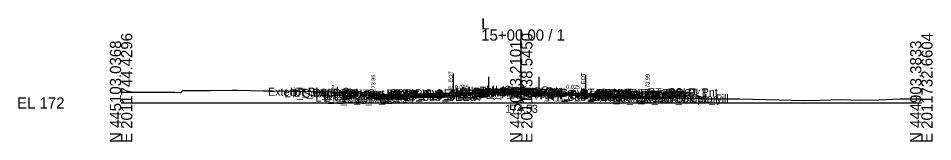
# Model space of a CAD drawing. Extents: x -26 to 4203, y -10 to 9526.
# Drawn here: x -25.7 to 202.8, y 4990.3 to 5021.2 of the extents above; entities that cross this region are included whole.
import ezdxf

# ---------------------------------------------------------------- set-up
doc = ezdxf.new("R2010")
doc.units = 0
for name, color, linetype in [('Default', 7, 'Continuous'), ('Exist CMT Pavement', 7, 'Continuous'), ('Exist Cross Section Cell', 7, 'Continuous'), ('Exist XS Center Line Elevation Label', 7, 'Continuous'), ('Exist XS Ground Line', 7, 'Continuous'), ('Prop CMT Conc Surface', 7, 'Continuous'), ('Prop CMT Concrete Structures', 7, 'Continuous'), ('Prop CMT Pvmt Course 1', 7, 'Continuous'), ('Prop CMT Pvmt Course 1 CG', 7, 'Continuous'), ('Prop CMT Pvmt Course 1 Wedge', 7, 'Continuous'), ('Prop CMT Pvmt Course 2', 7, 'Continuous'), ('Prop CMT Pvmt Course 2 Wedge', 7, 'Continuous'), ('Prop CMT Pvmt Course 3', 7, 'Continuous'), ('Prop CMT Pvmt Surface', 7, 'Continuous'), ('Prop CMT Pvmt Wedge Surface 1', 7, 'Continuous'), ('Prop CMT Pvmt Wedge Surface 2', 7, 'Continuous'), ('Prop CMT Pvmt Wedge Surface 3', 7, 'Continuous'), ('Prop CMT Slope Grass', 7, 'Continuous'), ('Prop CMT Subgrade Earthwork', 7, 'Continuous'), ('Prop XS Hydro Elevations', 7, 'Continuous'), ('Prop XS Label Text', 7, 'Continuous'), ('Prop XS SE Text', 7, 'Continuous'), ('Prop XS Side Slope Text', 7, 'Continuous'), ('Scratch_Level_0', 7, 'Continuous'), ('Scratch_Level_3', 7, 'Continuous')]:
    doc.layers.add(name, color=color, linetype=linetype)

msp = doc.modelspace()

# ---------------------------------------------------------------- linework, layer by layer
at = {"layer": 'Exist CMT Pavement'}
for points in [[(100, 5002.53), (99.08, 5002.54), (98.16, 5002.55), (97.34, 5002.55), (95.64, 5002.54), (94.98, 5002.54), (94.18, 5002.54), (93.53, 5002.54), (93.15, 5002.53), (91.11, 5002.52), (90.67, 5002.51), (90.28, 5002.51), (88.12, 5002.47), (85.72, 5002.44), (85.61, 5002.44), (85.26, 5002.43), (83.89, 5002.41), (83.13, 5002.4), (83, 5002.4), (81.97, 5002.39), (81.35, 5002.38), (81.35, 5002.38)], [(100, 5002.53), (100.66, 5002.53), (102.05, 5002.5), (103.13, 5002.48), (104.11, 5002.47), (104.98, 5002.47), (105.23, 5002.46), (105.64, 5002.45), (106.79, 5002.4), (108.16, 5002.35), (109.72, 5002.29), (110.69, 5002.26), (111.54, 5002.22), (113.18, 5002.14), (115.03, 5002.06), (115.68, 5002.04), (115.83, 5002.03), (116.08, 5002.02), (116.46, 5001.99), (117.25, 5001.94)]]:
    msp.add_lwpolyline(points, dxfattribs=at)
at = {"layer": 'Exist Cross Section Cell'}
for p, q in [((100, 5000), (100, 5018.37)), ((0, 5000), (100, 5000)), ((100, 5000), (200, 5000))]:
    msp.add_line(p, q, dxfattribs=at)
at = {"layer": 'Exist XS Ground Line'}
msp.add_lwpolyline([(0, 5002.68), (13.44, 5002.7), (15.02, 5002.59), (15.44, 5003.09), (22.37, 5003.11), (27.73, 5003.23), (29.13, 5003.23), (35.62, 5003.06), (37.77, 5003.03), (42.17, 5002.94), (44.79, 5002.98), (49.29, 5002.88), (51.69, 5002.82), (62.74, 5002.38), (66.97, 5002.11), (77.65, 5002.31), (81.35, 5002.38), (81.97, 5002.39), (83, 5002.4), (83.89, 5002.41), (85.26, 5002.43), (85.72, 5002.44), (88.12, 5002.47), (90.28, 5002.51), (90.67, 5002.51), (91.11, 5002.52), (93.15, 5002.53), (93.53, 5002.54), (94.18, 5002.54), (94.98, 5002.54), (95.64, 5002.54), (97.34, 5002.55), (98.16, 5002.55), (99.08, 5002.54), (100, 5002.53), (100.66, 5002.53), (102.05, 5002.5), (103.13, 5002.48), (104.11, 5002.47), (104.98, 5002.47), (105.64, 5002.45), (106.79, 5002.4), (108.16, 5002.35), (109.72, 5002.29), (110.69, 5002.26), (111.54, 5002.22), (113.18, 5002.14), (115.03, 5002.06), (116.08, 5002.02), (116.46, 5001.99), (117.25, 5001.94), (127.23, 5001.69), (134.52, 5001.49), (142.12, 5001.18), (144.54, 5001.12), (147.26, 5001.04), (154.56, 5001.01), (161.05, 5000.88), (164.58, 5000.8), (170.51, 5000.64), (174.6, 5000.72), (179.97, 5000.82), (184.61, 5000.72), (189.43, 5000.77), (194.63, 5000.99), (198.89, 5001.02), (200, 5001.01)], dxfattribs=at)
at = {"layer": 'Prop CMT Conc Surface'}
for points in [[(136.07, 5002.58), (141.07, 5002.68)], [(63.05, 5001.86), (63.05, 5002.36), (62.55, 5002.36)], [(65.05, 5001.99), (63.05, 5001.86)], [(129.57, 5002.12), (131.57, 5001.99)], [(131.57, 5001.99), (131.57, 5002.49), (132.07, 5002.49)]]:
    msp.add_lwpolyline(points, dxfattribs=at)
at = {"layer": 'Prop CMT Concrete Structures'}
for points in [[(98.45, 5003.29), (92.66, 5003.08), (91.91, 5002.83), (91.9, 5002.66)], [(91.9, 5002.66), (100, 5002.86), (104.49, 5002.75)], [(104.49, 5002.75), (104.48, 5002.92), (103.73, 5003.17), (98.45, 5003.29)], [(141.07, 5002.68), (136.07, 5002.58)], [(136.07, 5002.58), (136.07, 5002.25)], [(141.07, 5002.35), (141.07, 5002.68)], [(65.05, 5001.99), (63.05, 5001.86), (63.05, 5002.36), (62.55, 5002.36)], [(62.55, 5002.36), (62.55, 5001.34), (65.05, 5001.41)], [(65.05, 5001.41), (65.05, 5001.99)], [(129.57, 5002.12), (131.57, 5001.99), (131.57, 5002.49), (132.07, 5002.49)], [(132.07, 5002.49), (132.07, 5001.48), (129.57, 5001.54)], [(129.57, 5001.54), (129.57, 5002.12)], [(136.07, 5002.25), (141.07, 5002.35)]]:
    msp.add_lwpolyline(points, dxfattribs=at)
at = {"layer": 'Prop CMT Pvmt Course 1'}
for points in [[(100, 5002.86), (65.05, 5001.99)], [(83, 5002.31), (100, 5002.74)], [(100, 5002.61), (100, 5002.86)], [(100, 5002.86), (129.57, 5002.12)], [(100, 5002.61), (100, 5002.86)], [(100, 5002.74), (100, 5002.61), (100, 5002.61)], [(116.08, 5002.34), (100, 5002.74)], [(100, 5002.74), (100, 5002.61), (100, 5002.61)], [(65.05, 5001.74), (81.35, 5002.15)], [(65.05, 5001.99), (65.05, 5001.74)], [(83, 5002.19), (83, 5002.31)], [(116.08, 5002.21), (116.08, 5002.34)], [(129.57, 5001.87), (117.25, 5002.18)], [(129.57, 5002.12), (129.57, 5001.87)]]:
    msp.add_lwpolyline(points, dxfattribs=at)
at = {"layer": 'Prop CMT Pvmt Course 1 CG'}
for points in [[(65.05, 5001.41), (62.05, 5001.33), (61.7, 5000.99)], [(61.7, 5000.99), (65.05, 5001.07)], [(65.05, 5001.07), (65.05, 5001.41)], [(129.57, 5001.54), (132.57, 5001.47), (132.91, 5001.12)], [(129.57, 5001.21), (129.57, 5001.54)], [(132.91, 5001.12), (129.57, 5001.21)]]:
    msp.add_lwpolyline(points, dxfattribs=at)
at = {"layer": 'Prop CMT Pvmt Course 1 Wedge'}
for points in [[(100, 5002.61), (99.08, 5002.59), (98.16, 5002.57), (97.35, 5002.55), (97.34, 5002.55), (95.64, 5002.54), (94.98, 5002.54), (94.18, 5002.54), (93.53, 5002.54), (93.15, 5002.53), (91.11, 5002.52), (91.08, 5002.52)], [(91.11, 5002.52), (93.15, 5002.57), (93.53, 5002.58), (94.18, 5002.59), (94.98, 5002.61), (95.64, 5002.63), (97.34, 5002.67), (98.16, 5002.69), (99.08, 5002.71), (100, 5002.74)], [(100, 5002.61), (100, 5002.74)], [(100, 5002.74), (100, 5002.61)], [(116.08, 5002.21), (115.83, 5002.22), (115.68, 5002.22), (115.03, 5002.24), (113.18, 5002.28), (111.54, 5002.32), (110.69, 5002.35), (109.72, 5002.37), (108.16, 5002.41), (106.79, 5002.44), (105.64, 5002.47), (105.23, 5002.48), (104.98, 5002.49), (104.11, 5002.51), (103.13, 5002.53), (102.05, 5002.56), (100.66, 5002.6), (100, 5002.61)], [(91.08, 5002.52), (91.11, 5002.52)], [(116.08, 5002.34), (116.08, 5002.21)]]:
    msp.add_lwpolyline(points, dxfattribs=at)
at = {"layer": 'Prop CMT Pvmt Course 2'}
for points in [[(83, 5002.19), (65.05, 5001.74)], [(65.05, 5001.41), (81.35, 5001.81)], [(65.05, 5001.74), (65.05, 5001.41)], [(83, 5001.85), (83, 5002.19)], [(116.08, 5001.88), (116.08, 5002.21)], [(116.08, 5002.21), (129.57, 5001.87)], [(129.57, 5001.54), (117.25, 5001.85)], [(129.57, 5001.87), (129.57, 5001.54)]]:
    msp.add_lwpolyline(points, dxfattribs=at)
at = {"layer": 'Prop CMT Pvmt Course 2 Wedge'}
for points in [[(98.16, 5002.57), (99.08, 5002.59), (100, 5002.61)], [(100, 5002.53), (100, 5002.61)], [(100, 5002.61), (100, 5002.53)], [(100, 5002.61), (100.66, 5002.6), (102.05, 5002.56), (103.13, 5002.53), (104.11, 5002.51), (104.98, 5002.49), (105.23, 5002.48), (105.64, 5002.47), (106.79, 5002.44), (108.16, 5002.41), (109.72, 5002.37), (110.69, 5002.35), (111.54, 5002.32), (113.18, 5002.28), (115.03, 5002.24), (115.68, 5002.22), (115.83, 5002.22), (116.08, 5002.21)], [(97.35, 5002.55), (98.16, 5002.57)], [(100, 5002.53), (99.08, 5002.54), (98.16, 5002.55), (97.35, 5002.55)], [(117.25, 5001.94), (116.46, 5001.99), (116.08, 5002.02), (115.83, 5002.03), (115.68, 5002.04), (115.03, 5002.06), (113.18, 5002.14), (111.54, 5002.22), (110.69, 5002.26), (109.72, 5002.29), (108.16, 5002.35), (106.79, 5002.4), (105.64, 5002.45), (105.23, 5002.46), (104.98, 5002.47), (104.11, 5002.47), (103.13, 5002.48), (102.05, 5002.5), (100.66, 5002.53), (100, 5002.53)], [(116.08, 5002.21), (116.08, 5001.97)]]:
    msp.add_lwpolyline(points, dxfattribs=at)
at = {"layer": 'Prop CMT Pvmt Course 3'}
for points in [[(83, 5001.85), (65.05, 5001.41)], [(65.05, 5001.07), (83, 5001.52)], [(65.05, 5001.41), (65.05, 5001.07)], [(83, 5001.52), (83, 5001.85)], [(116.08, 5001.88), (129.57, 5001.54)], [(116.08, 5001.54), (116.08, 5001.88)], [(129.57, 5001.21), (116.08, 5001.54)], [(129.57, 5001.54), (129.57, 5001.21)]]:
    msp.add_lwpolyline(points, dxfattribs=at)
at = {"layer": 'Prop CMT Pvmt Surface'}
for points in [[(100, 5002.86), (65.05, 5001.99)], [(100, 5002.86), (129.57, 5002.12)]]:
    msp.add_lwpolyline(points, dxfattribs=at)
at = {"layer": 'Prop CMT Pvmt Wedge Surface 1'}
for points in [[(100, 5002.74), (83, 5002.31)], [(100, 5002.74), (116.08, 5002.34)], [(81.35, 5002.15), (65.05, 5001.74)], [(65.05, 5001.74), (65.05, 5001.99)], [(83, 5002.31), (83, 5002.19)], [(116.08, 5002.34), (116.08, 5002.21)], [(117.25, 5002.18), (129.57, 5001.87)], [(129.57, 5001.87), (129.57, 5002.12)]]:
    msp.add_lwpolyline(points, dxfattribs=at)
at = {"layer": 'Prop CMT Pvmt Wedge Surface 2'}
for points in [[(100, 5002.61), (83, 5002.19)], [(100, 5002.61), (116.08, 5002.21)], [(65.05, 5001.74), (65.05, 5001.99)], [(129.57, 5001.87), (129.57, 5002.12)]]:
    msp.add_lwpolyline(points, dxfattribs=at)
at = {"layer": 'Prop CMT Pvmt Wedge Surface 3'}
for points in [[(65.05, 5001.41), (65.05, 5001.99)], [(100, 5002.28), (83, 5001.85)], [(100, 5002.28), (116.08, 5001.88)], [(129.57, 5001.54), (129.57, 5002.12)]]:
    msp.add_lwpolyline(points, dxfattribs=at)
at = {"layer": 'Prop CMT Slope Grass'}
for p, q in [((52.32, 5002.79), (53.05, 5002.55)), ((141.57, 5002.68), (146.43, 5001.06))]:
    msp.add_line(p, q, dxfattribs=at)
for points in [[(132.07, 5002.49), (141.57, 5002.68)], [(62.55, 5002.36), (53.05, 5002.55)]]:
    msp.add_lwpolyline(points, dxfattribs=at)
at = {"layer": 'Prop CMT Subgrade Earthwork'}
for points in [[(65.05, 5001.07), (61.7, 5000.99), (60.29, 5002.4)], [(83, 5001.52), (65.05, 5001.07)], [(83, 5001.52), (83, 5002.4)], [(116.08, 5001.54), (116.08, 5002.02)], [(116.08, 5001.54), (129.57, 5001.21)], [(129.57, 5001.21), (132.91, 5001.12), (134.33, 5002.54)]]:
    msp.add_lwpolyline(points, dxfattribs=at)
at = {"layer": 'Prop XS Label Text'}
for p, q in [((83, 5007.4), (83, 5002.4)), ((116.08, 5007.02), (116.08, 5002.02))]:
    msp.add_line(p, q, dxfattribs=at)
at = {"layer": 'Scratch_Level_3'}
for p, q in [((91.9, 5002.66), (91.9, 5006.5)), ((104.49, 5002.75), (104.49, 5006.5))]:
    msp.add_line(p, q, dxfattribs=at)
msp.add_lwpolyline([(100, 5002.74), (100.66, 5002.72), (102.05, 5002.69), (103.13, 5002.66), (104.11, 5002.64), (104.98, 5002.61), (105.23, 5002.61), (105.64, 5002.6), (106.79, 5002.57), (108.16, 5002.53), (109.72, 5002.5), (110.69, 5002.47), (111.54, 5002.45), (113.18, 5002.41), (115.03, 5002.36), (115.68, 5002.35), (115.83, 5002.34), (116.08, 5002.34)], dxfattribs=at)

# ---------------------------------------------------------------- texts
at = {"layer": 'Default'}
msp.add_text('-', height=0.0001, dxfattribs=at).set_placement((0, 5000))
at = {"layer": 'Exist Cross Section Cell'}
for s, p in [('L', (90, 5018.37)), ('15+00.00 / 1', (90, 5015.57)), ('EL 172', (-26, 4998.6))]:
    msp.add_text(s, height=2.8, dxfattribs=at).set_placement(p)
for s, p in [('E 2011744.4296', (2.8, 4990)), ('E 2011738.5450', (102.8, 4990)), ('E 2011732.6604', (202.8, 4990)), ('N 445103.0368', (0, 4990)), ('N 445003.2101', (100, 4990)), ('N 444903.3833', (200, 4990))]:
    msp.add_text(s, height=2.8, rotation=90, dxfattribs=at).set_placement(p)
at = {"layer": 'Exist XS Center Line Elevation Label'}
msp.add_text('174.53', height=2, dxfattribs=at).set_placement((95.99, 4997.53))
at = {"layer": 'Prop XS Hydro Elevations'}
for s, p in [('173.86', (63.55, 5002.86)), ('173.99', (132.07, 5002.99))]:
    msp.add_text(s, height=1, rotation=90, dxfattribs=at).set_placement(p)
at = {"layer": 'Prop XS Label Text'}
for p in [(82.9, 5003.43), (115.98, 5003.05)]:
    msp.add_text('E. EOT', height=1, rotation=90, dxfattribs=at).set_placement(p)
at = {"layer": 'Prop XS SE Text'}
for rotation, p in [(1.4324, (83.41, 5003.45)), (358.5686, (111.23, 5003.57))]:
    msp.add_text('0.025', height=1, rotation=rotation, dxfattribs=at).set_placement(p)
at = {"layer": 'Prop XS Side Slope Text'}
for p in [(52.32, 5003.59), (142.78, 5002.8)]:
    msp.add_text('3:1', height=1, rotation=341.5651, dxfattribs=at).set_placement(p)
at = {"layer": 'Scratch_Level_0'}
for s, p in [('Exterior Boundary', (36.72, 5001.78)), ('LT_Sub_Trench_Out_DLT', (40.86, 5001.4)), ('LT_Slope_Cut', (42.22, 5001.78)), ('LT_CSLP_Pnt', (43.22, 5001.55)), ('LT_CG_Top_Face', (50.3, 5001.36)), ('LT_CG_Top_BOC', (50.83, 5001.36)), ('LT_CG_Top_Gut', (51.28, 5000.86)), ('LT_PV2_OEOT', (55.22, 5000.74)), ('LT_PV1_OEOT', (55.79, 5000.99)), ('LT_PV_Sub_Tie_Out', (66.31, 5001.38)), ('LT_PV_OEEOP_EG', (68.89, 5001.38)), ('LT_Sub_OEEOP', (70.56, 5000.48)), ('LT_PV2_OEEOP', (70.65, 5001.15)), ('LT_PV3_OEEOP', (70.65, 5000.81)), ('LT_PV1_OEEOP', (71.22, 5001.27)), ('MI_Face In', (83.47, 5001.82)), ('MI_Bot In', (84.45, 5001.65)), ('MI_Top In', (85.18, 5002.07)), ('RT_PV_IEEOP_EG', (88.14, 5001.53)), ('LT_PV_IEEOP_EG', (88.19, 5001.53)), ('RT_PV2_IEEOP', (89.91, 5001.61)), ('RT_PV3_IEEOP', (89.91, 5001.28)), ('LT_PV2_IEEOP', (89.95, 5001.61)), ('LT_PV3_IEEOP', (89.95, 5001.28)), ('RT_PV1_IEEOP', (90.47, 5001.74)), ('LT_PV1_IEEOP', (90.52, 5001.74)), ('MI_Crown', (91.19, 5002.28)), ('PV2_PGL', (93.91, 5001.61)), ('PV1_PGL', (94.47, 5001.86)), ('MI_Face Out', (94.93, 5001.91)), ('MI_Top Out', (95.14, 5002.16)), ('MI_Bot', (95.18, 5001.86)), ('MI_Bot Out', (95.93, 5001.75)), ('RT_PV_Sub_Tie_Out', (102.13, 5000.94)), ('RT_PV_OEEOP_EG', (104.74, 5000.94)), ('RT_Sub_OEEOP', (106.41, 5000.51)), ('RT_PV2_OEEOP', (106.51, 5001.18)), ('RT_PV3_OEEOP', (106.51, 5000.85)), ('RT_PV1_OEEOP', (107.07, 5001.31)), ('RT_Sub_Trench_Out_DLT', (114.73, 5001.54)), ('RT_CG_Top_Face', (118.67, 5001.5)), ('RT_PV2_OEOT', (119.58, 5000.88)), ('RT_CG_Top_Gut', (119.64, 5001)), ('RT_PV1_OEOT', (120.15, 5001.13)), ('RT_CG_Top_BOC', (120.19, 5001.5)), ('RT_CSLP_Pnt', (131.58, 5001.69)), ('LT_CG1_Shelf_Out', (48.6, 5000.33)), ('LT_CG_Bot_BOC', (50.86, 5000.34)), ('LT_Sub_OEOP', (51.81, 4999.99)), ('LT_CG_Bot_IE', (54.96, 5000.41)), ('LT_Sub_OEOT', (55.13, 5000.07)), ('LT_PV3_OEOT', (55.22, 5000.41)), ('RT_CG1_Shelf_Out', (118.96, 5000.47)), ('RT_CG_Bot_IE', (119.32, 5000.54)), ('RT_Sub_OEOT', (119.49, 5000.21)), ('RT_PV3_OEOT', (119.58, 5000.54)), ('RT_CG_Bot_BOC', (120.22, 5000.48)), ('RT_Sub_OEOP', (122.86, 5000.13)), ('Exterior Boundary', (128.73, 5000.12)), ('RT_Slope_Fill', (135.06, 5000.12))]:
    msp.add_text(s, height=2, dxfattribs=at).set_placement(p)

doc.saveas('drawing.dxf')
